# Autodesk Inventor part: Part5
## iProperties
Shininess: 64.0
Length Units: 11269
Angle Units: 11279
Time Units: 11290
Mass Units: 11283
Length Display Precision: 3
Angle Display Precision: 2
Compacted: True
Part Number: Part5
Document SubType Name: Modeling
Created: 2002-12
Designer: deepak
Density: 1 g/cm^3
Density: 0.0
Volumn: 0.0
Area: 0.0
PropertySet Name: Model Information
Control State: 0
Master: False
Checked Out: False
Author: deepak
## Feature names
1. Extrusion1
2. Fillet1
